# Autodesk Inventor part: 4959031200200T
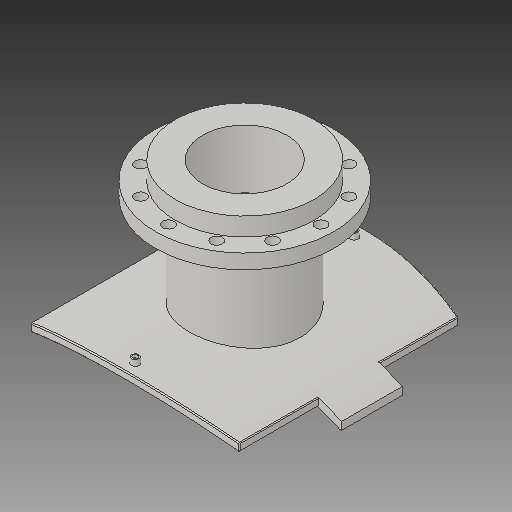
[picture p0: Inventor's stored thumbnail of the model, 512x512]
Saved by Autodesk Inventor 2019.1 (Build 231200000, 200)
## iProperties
Created: 2017-10
Part Number: 4959031200200T
Material: Generic
Description: PLASSON FLANGED BRANCH SADDLE 1200X200
Document SubType Name: Modeling
Designer: KIM
Mass: 2339.99 g
Surface Area: 3251.55 cm^2
Volume: 2339.99 cm^3
Density: 1 g/cm^3
Appearance: Default
Author: KIM
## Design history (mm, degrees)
derived "495904_495903.ipt"
feature "Solid1::495904_495903.ipt"
feature "Solid2::495904_495903.ipt"
tag "TaggingFeature1"
body "Solid1"
other parameters: "d1" = 15, "d2" = 402.3, "d4" = 0, "d6" = 117.5, "d7" = 0, "d12" = 625.6, "d13" = 14, "d14" = 211.5, "d16" = 5 deg, "d18" = 4, "d19" = 14, "d20" = 0, "d21" = 3, "d22" = 0, "d23" = 865, "d36" = 211.5, "d38" = 0, "d39" = 2, "d41" = 163, "d42" = 268, "d43" = 344, "d46" = 214.4, "d47" = 16, "d48" = 10.4, "d49" = 175, "d51" = 1224, "d53" = 0, "d54" = 22, "d55" = 147.5, "d57" = 0, "d59" = 360 deg, "d61" = 28, "d63" = 0, "d67" = 15, "d68" = 125, "d70" = 0, "d71" = 2, "d72" = 447, "d_1" = 268, "B_" = 447, "x_" = 15, "D_" = 16, "DN_" = 163, "D_1" = 344, "t_" = 28, "s_" = 22, "Dp_" = 295
